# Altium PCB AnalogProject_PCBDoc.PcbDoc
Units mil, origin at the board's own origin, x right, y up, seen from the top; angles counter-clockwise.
Board outline 2357.65 x 1577.53 mil, 2 copper layers (Top Layer, Bottom Layer); 20 components, 11 nets, 48 pads, 3 vias.
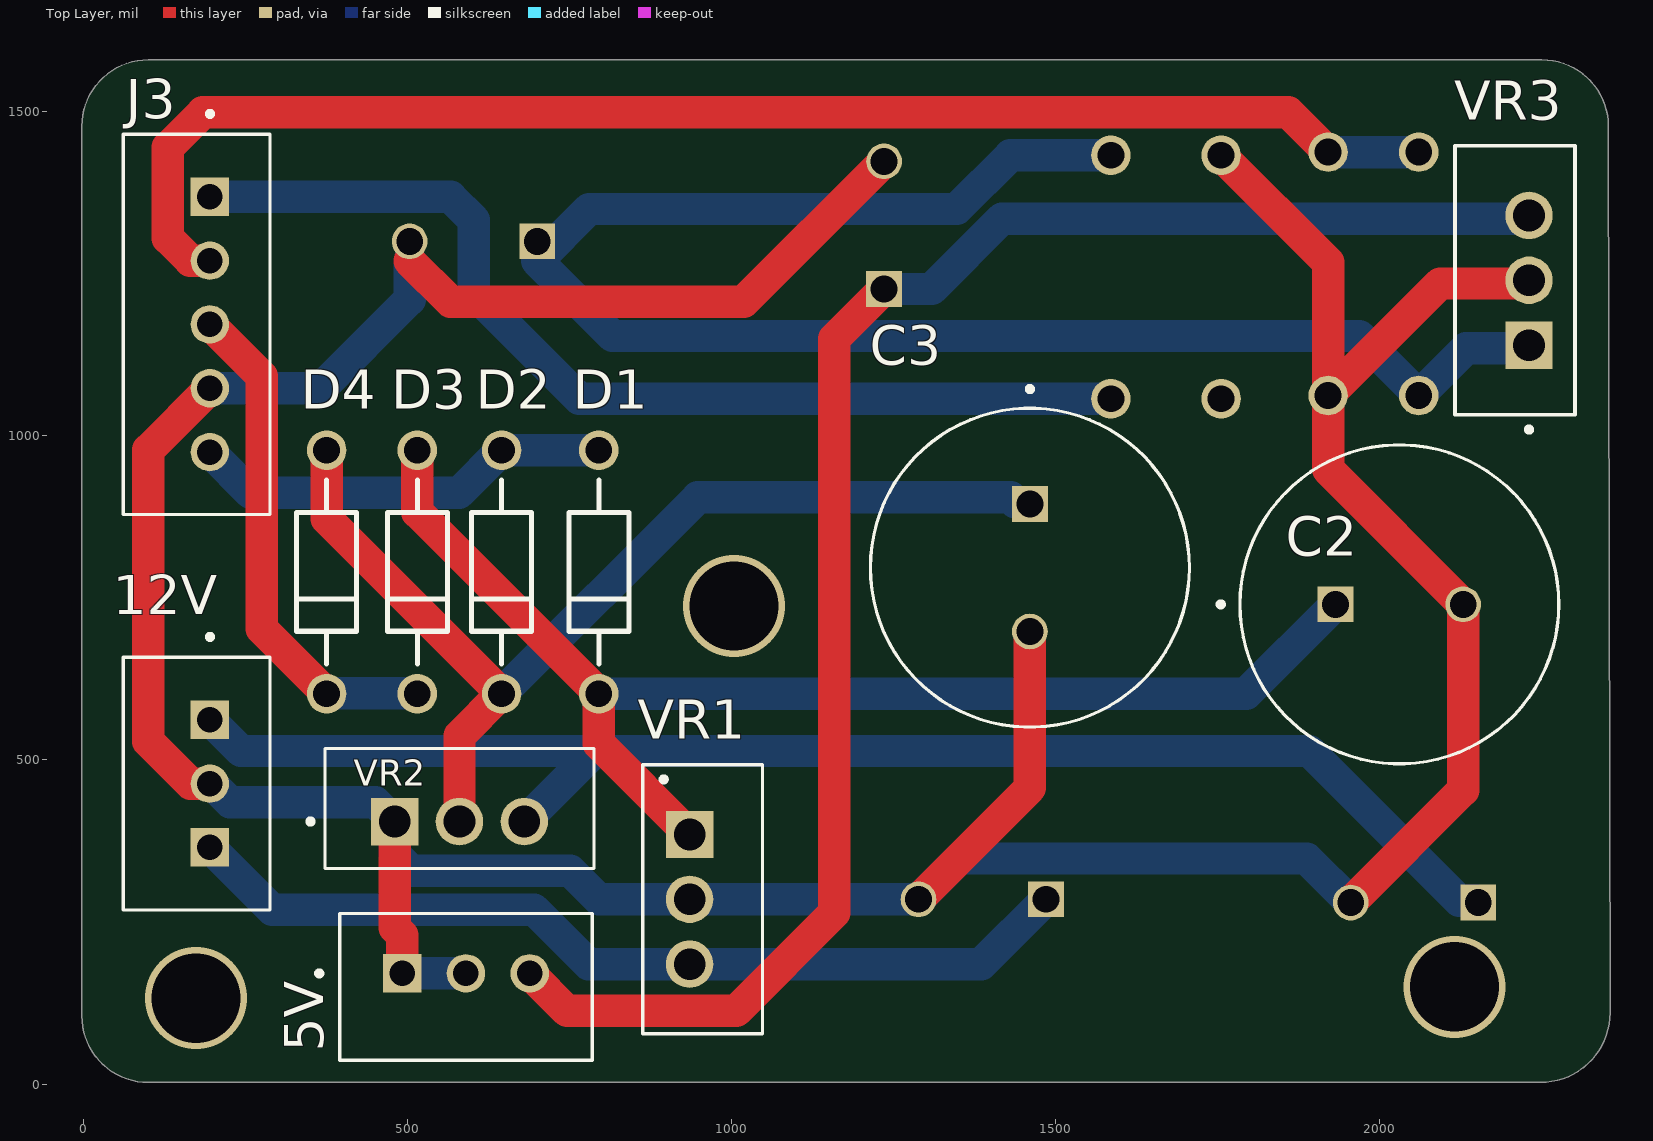
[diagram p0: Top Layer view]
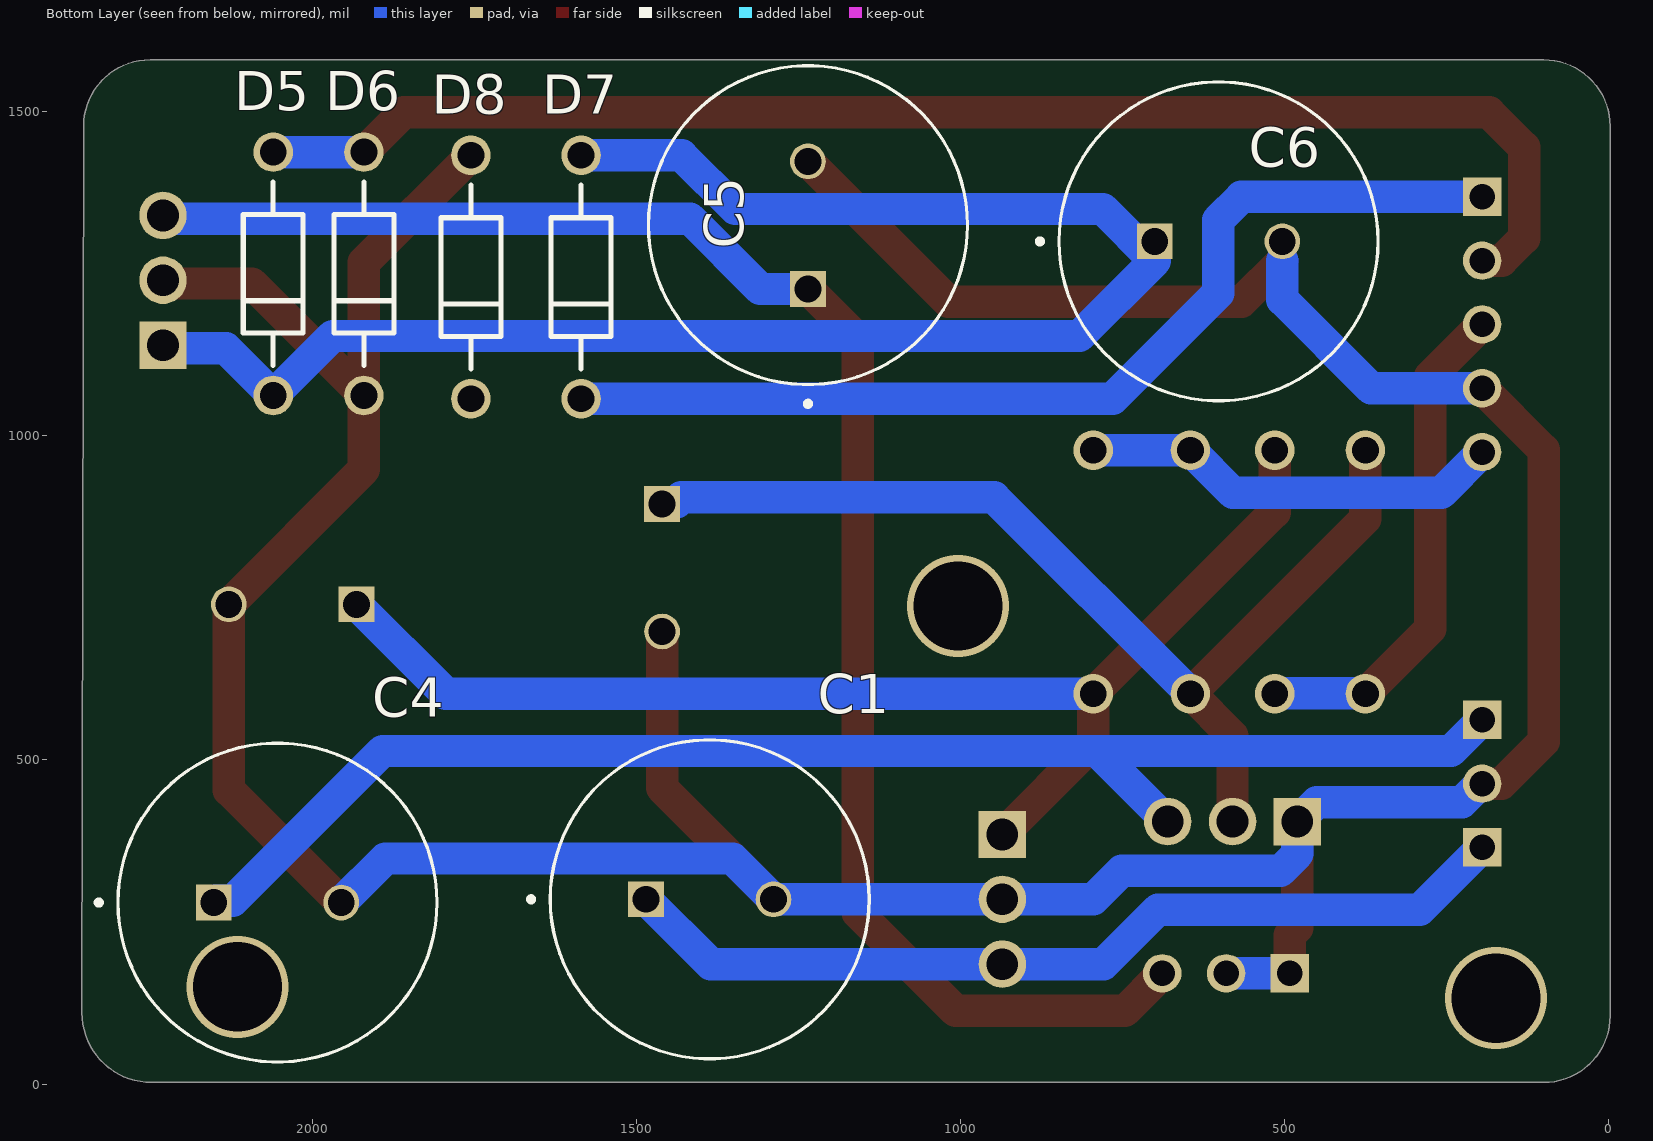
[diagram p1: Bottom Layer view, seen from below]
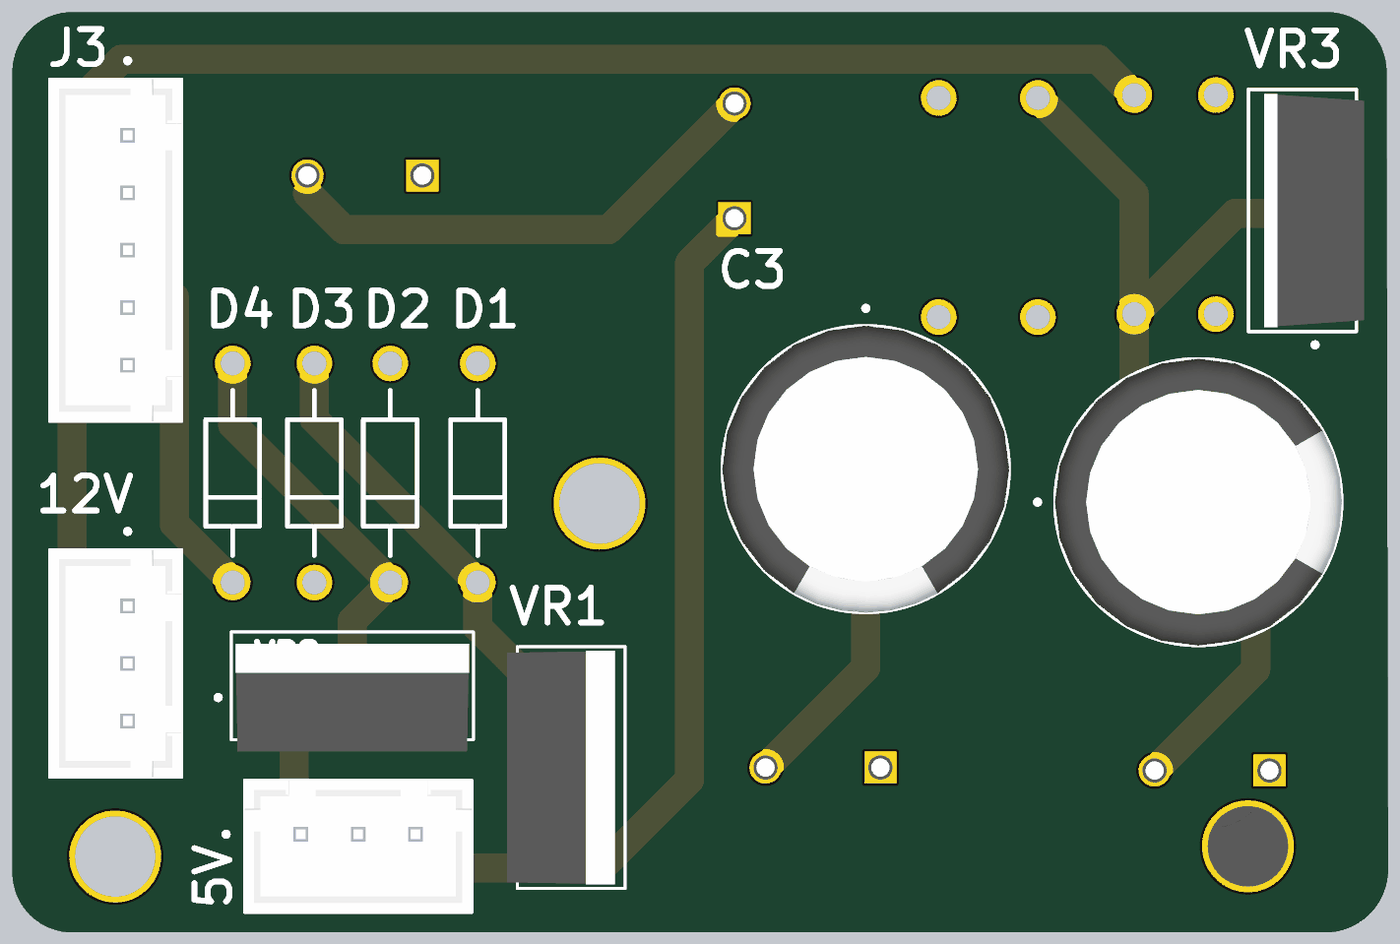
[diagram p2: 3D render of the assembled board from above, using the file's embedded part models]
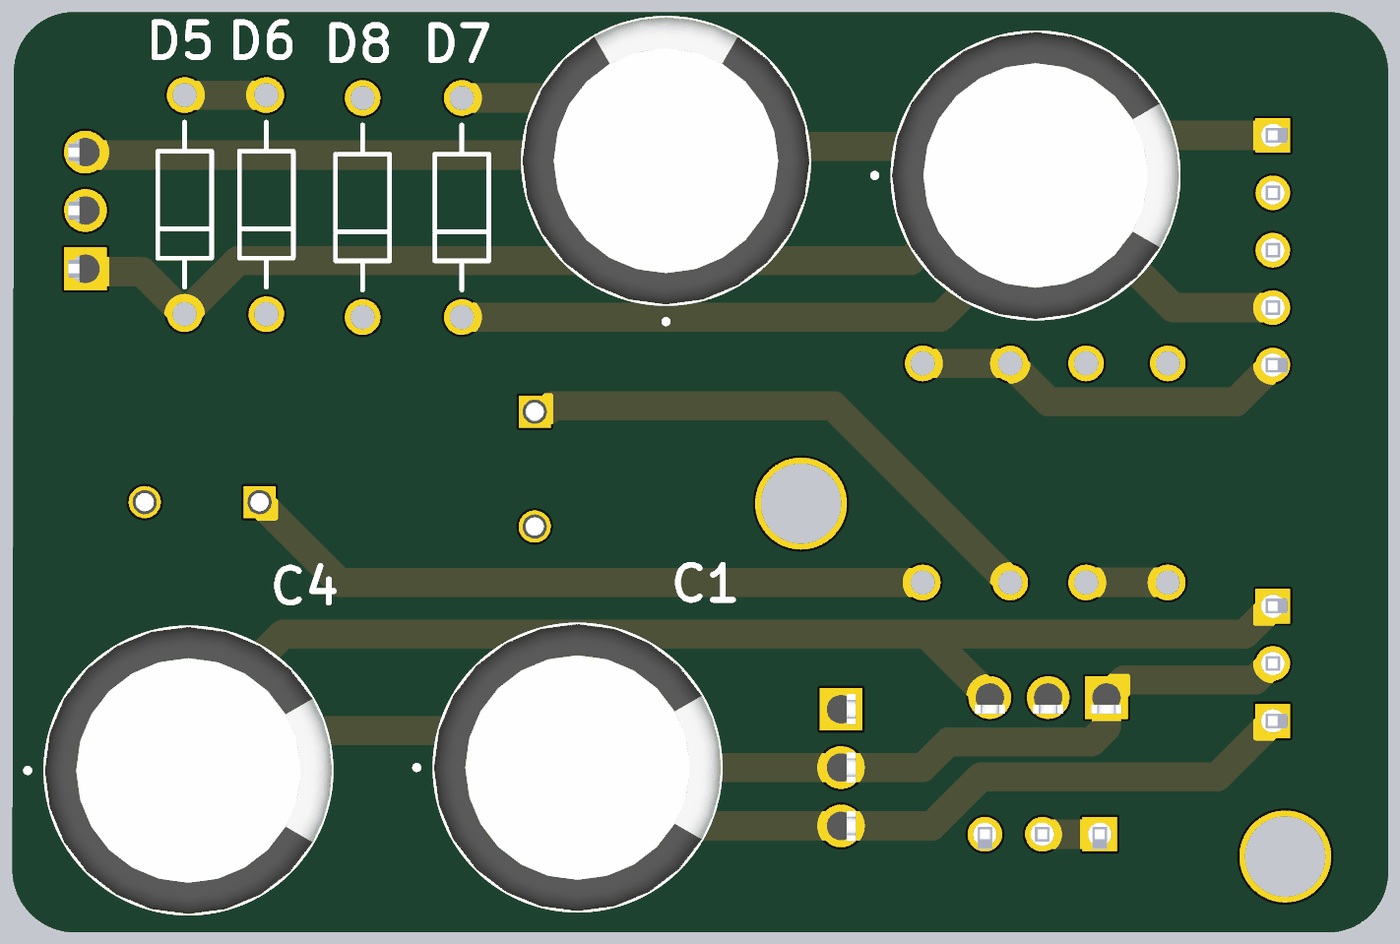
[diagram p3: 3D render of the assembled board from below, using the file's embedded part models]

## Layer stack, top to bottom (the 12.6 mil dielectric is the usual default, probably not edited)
Top Solder: solder mask 0.4, Solder Resist, Dk 3.5
Top Layer: signal copper 1.4
Dielectric 1: dielectric 12.6, FR-4, Dk 4.8
Bottom Layer: signal copper 1.4
Bottom Solder: solder mask 0.4, Solder Resist, Dk 3.5

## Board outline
-2.53,105 ccw(c100,105) 100,2.47 2247.47,2.47 ccw(c2247.47,110.12) 2355.12,110.12 2352.53,1477.47 ccw(c2250,1477.47) 2250,1580 100,1580 ccw(c100,1477.47) -2.53,1477.47

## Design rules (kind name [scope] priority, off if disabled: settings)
Clearance [All] p1: gap=10 ignorepadtopadclearanceinfootprint=FALSE
Height [All] p1: minheight=0 maxheight=2362.2 prefheight=500
PolygonConnect [All] p1: connectstyle=Relief reliefconductorwidth=10 reliefentries=4 polygonreliefangle="90 Angle" airgapwidth=10
RoutingVias [All] p1: holewidth=28 width=50 viastyle="Through Hole" minholewidth=28 minwidth=50 maxholewidth=28 maxwidth=50
SolderMaskExpansion [All] p1: expansion=4 istentingtop=FALSE
SupplyNets "Schematic Supply Nets" [InNet('GND')] p1: voltage=0.000
Width [All] p1: maxlimit=60 minlimit=30 preferedwidth=50
29 further rules are at their usual default settings.

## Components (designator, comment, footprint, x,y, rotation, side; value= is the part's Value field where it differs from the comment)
5V "+" JST_B3B-XH-A#1 590,150 r180 top (schematic designator J1)
12V "+" JST_B3B-XH-A#2 174.33,463.43 r90 top (schematic designator J2)
C1 "2200uF Cap" "2200uF Cap" 1386.57,285 r180 bottom
C2 "2200uF Cap" "2200uF Cap" 2030,740 r0 top
C3 "2200uF Cap" "2200uF Cap" 1460,796.57 r270 top
C4 "2200uF Cap" "2200uF Cap" 2053.43,280 r180 bottom
C5 "2200uF Cap" "2200uF Cap" 1235,1325 r90 bottom
C6 "2200uF Cap" "2200uF Cap" 601.57,1300 r180 bottom
D1 "1N4001G" 1N4001_diode 795,790 r90 top
D2 "1N4001G" 1N4001_diode 645,790 r90 top
D3 "1N4001G" 1N4001_diode 515,790 r90 top
D4 "1N4001G" 1N4001_diode 375,790 r90 top
D5 "1N4001G" 1N4001_diode 2060,1250 r90 bottom
D6 "1N4001G" 1N4001_diode 1920,1250 r90 bottom
D7 "1N4001G" 1N4001_diode 1585,1245 r90 bottom
D8 "1N4001G" 1N4001_diode 1755,1245 r90 bottom
J3 "B5B-XH-A" JST_B5B-XH-A 174.33,1171.85 r90 top
VR1 "LM7812CT/NOPB" LM7812 935,285 r270 top
VR2 "LM7912CT/NOPB" LM7912 580,405 r0 top
VR3 "LM7805CT/NOPB" LM7805 2230,1140 r90 top

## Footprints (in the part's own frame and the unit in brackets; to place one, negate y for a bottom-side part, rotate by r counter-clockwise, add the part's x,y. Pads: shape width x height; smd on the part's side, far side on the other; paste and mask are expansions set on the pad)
1N4001_diode [mm] "AXIAL, 2-Leads, Diameter 2.35mm"
  round 1.55 hole 1.05: 1(-4.77,0) 2(4.77,0)
  silkscreen extent -3.6,-1.18 3.6,1.18
"2200uF Cap" [mm]
  rect 1.4x1.4 hole 1.05: 1(-2.5,0)
  round 1.4 hole 1.05: 2(2.5,0)
  silkscreen extent -7.1,-6.25 6.25,6.25, body extent -6.22,-6.25 6.25,6.25, height 35
JST_B3B-XH-A#1 [mm]
  rect 1.508x1.508 / inner round 1.508 / far side rect 1.508x1.508 hole 1: 1(2.5,-0.525)
  round 1.508 hole 1: 2(0,-0.525) 3(-2.5,-0.525)
  silkscreen extent -4.95,-2.88 5.85,2.87, body extent -4.95,-2.88 4.95,2.88, height 7
JST_B3B-XH-A#2 [mm]
  rect 1.508x1.508 / inner round 1.508 / far side rect 1.508x1.508 hole 1: 1(2.5,-0.525)
  round 1.508 hole 1: 2(0,-0.525)
  rect 1.508x1.508 hole 1: 3(-2.5,-0.525)
  silkscreen extent -4.95,-2.88 5.85,2.87, body extent -4.95,-2.88 4.95,2.88, height 7
JST_B5B-XH-A [mm]
  rect 1.508x1.508 / inner round 1.508 / far side rect 1.508x1.508 hole 1: 1(5,-0.525)
  round 1.508 hole 1: 2(2.5,-0.525) 3(0,-0.525) 4(-2.5,-0.525) 5(-5,-0.525)
  silkscreen extent -7.45,-2.88 8.35,2.87, body extent -7.45,-2.88 7.45,2.88, height 7
LM7805 [mm]
  rect 1.86x1.86 / inner round 1.86 / far side rect 1.86x1.86 hole 1.24: 1(0,0)
  round 1.86 hole 1.24: 2(2.54,0) 3(5.08,0)
  silkscreen extent -3.41,-1.8 7.81,2.9, body extent -2.54,-2.14 7.62,2.21, height 20.4
LM7812 [mm]
  rect 1.86x1.86 / inner round 1.86 / far side rect 1.86x1.86 hole 1.24: 1(-2.54,0)
  round 1.86 hole 1.24: 2(0,0) 3(2.54,0)
  silkscreen extent -5.27,-1.84 5.27,2.86, body extent -5.08,-2.29 5.08,2.41, height 15.49
LM7912 [mm]
  rect 1.86x1.86 / inner round 1.86 / far side rect 1.86x1.86 hole 1.24: 1(-2.54,0)
  round 1.86 hole 1.24: 2(0,0) 3(2.54,0)
  silkscreen extent -5.94,-1.84 5.27,2.86, body extent -5.08,-2.35 5.08,2.35, height 15.49

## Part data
5V 12V: library part B3B-XH-A, "Connector Header Through Hole 3 position 0.098 (2.50mm)", Package=None
C1 C2 C3 C4 C5 C6: "2200 ÂµF 25 V Aluminum Electrolytic Capacitors Radial, Can - 5000 Hrs @ 105Â°C", Package="RADIAL-2 Panasonic"
D1 D2 D3 D4 D5 D6 D7 D8: library part CMP-0902-00120-1, "Diode, Rectifier, Standard, Vr 50V, If 1A, Pkg SOD57, Vf 0.93V, Tj +175C, Cs 30A, Ir 1UA", Average Rectified Current=1A, Breakdown Voltage=50V, Forward Voltage=1.1V, Manufacturer="On Semiconductor", Manufacturer Lifecycle Status=ACTIVE, Max Forward Surge Current (Ifsm)=30A, Max Operating Temperature=150°C, Min Operating Temperature=-65°C, Peak Reverse Current=10µA, Supplier Part Number=1N4001GOS-ND
J3: "Connector Header Through Hole 5 position 0.098 (2.50mm)", Package=None
VR1: "1.5-A, 30-V, linear voltage regulator", Package="TO-220-3 Texas Instruments"
VR2: "1.5-A, negative linear voltage regulator", Package="TO-220-3 Texas Instruments"
VR3: "Linear Voltage Regulator IC Positive Fixed 1 Output 1.5A TO-220-3", Package="TO-220-3 ON Semiconductor"

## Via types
v1: diameter 157.48, hole 137.8, Top Layer to Bottom Layer, 3 vias

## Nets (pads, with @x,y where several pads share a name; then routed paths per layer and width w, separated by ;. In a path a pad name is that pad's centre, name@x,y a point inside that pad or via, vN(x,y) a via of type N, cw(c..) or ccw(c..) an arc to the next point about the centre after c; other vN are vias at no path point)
5V: 5V.3 C5.1 VR3.3 | length 2592.5
  Top Layer w50: 5V.3 746.1,113 1007,113 1158,264 1158,1149.57 C5.1
  Bottom Layer w50: C5.1 1308.57,1226.57 1417,1335 2208.58,1335 2209.13,1335.56 2225.56,1335.56 VR3.3
+Vs: 12V.3 C1.1 VR1.3 | length 1406
  Bottom Layer w50: 12V.3 291,269 695,269 779,185 VR1.3 1385,185 C1.1
-Vs: 12V.1 C4.1 VR2.3 | length 2227.5
  Bottom Layer w50: 12V.1 243,513.85 788.85,513.85 ; VR2.3 788.85,513.85 ; C4.1 2149.29,282.56 2122.44,282.56 1891.15,513.85 788.85,513.85
GND: 5V.1 5V.2 12V.2 C1.2 C2.2 C3.2 C4.2 C5.2 C6.2 D6.1 D8.2 J3.4 VR1.2 VR2.1 VR3.2 | length 6480.8
  Top Layer w50: 12V.2 165,463.43 100,528.43 100,978.43 J3.4 ; VR2.1 480,241.39 491.57,229.82 5V.1 ; 503.15,1270 566.15,1207 1018.57,1207 C5.2 ; C1.2 1460,456.85 C3.2 ; D8.2 1920,1267.8 D6.1 ; C4.2 2128.43,453.43 C2.2 1920,948.43 D6.1 ; VR3.2 2225.56,1235.56 2209.13,1235.56 2208.58,1235 2092.8,1235 D6.1
  Bottom Layer w50: 12V.2 197.54,463.43 225.96,435 450,435 VR2.1 480,355 506,329 751,329 795,285 VR1.2 C1.2 1351.15,348 1887,348 C4.2 ; J3.4 366.43,1073.43 503.15,1210.15 503.15,1270 ; 5V.1 5V.2
NetC2_1: C2.1 D1.1 D3.2 VR1.1 | length 1960.4
  Top Layer w50: D3.2 515,882.2 D1.1 795,525 VR1.1
  Bottom Layer w50: D1.1 1793.78,602.2 C2.1
NetC3_1: C3.1 D2.1 D4.2 VR2.2 | length 1656.1
  Top Layer w50: D4.2 375,872.2 D2.1 580,537.2 VR2.2
  Bottom Layer w50: D2.1 947.8,905 1430.24,905 1437.68,897.56 1457.44,897.56 C3.1
NetC6_1: C6.1 D5.1 D7.2 VR3.1 | length 2600.7
  Bottom Layer w50: D7.2 1429.8,1432.8 1347.01,1350 780,1350 700,1270 816,1154 1968.2,1154 D5.1 2132.8,1135 2225,1135 VR3.1
NetD1_2: D1.2 D2.2 J3.5 | length 653.3
  Bottom Layer w50: J3.5 258,912 579.2,912 D2.2 D1.2
NetD3_1: D3.1 D4.1 J3.3 | length 784.5
  Top Layer w50: J3.3 275,1091.85 275,702.2 D4.1
  Bottom Layer w50: D4.1 375.38,602.59 514.62,602.59 D3.1
NetD5_2: D5.2 D6.2 J3.2 | length 2197.1
  Top Layer w50: J3.2 164.72,1270.28 130,1305 130,1445 184,1499 1858.8,1499 D6.2
  Bottom Layer w50: D6.2 D5.2
NetD7_1: D7.1 J3.1 | length 1585.1
  Bottom Layer w50: J3.1 566.3,1368.7 602,1333 602,1220.2 765,1057.2 D7.1
pads on no net: D8.1
copper on no net:
  other v1: 173.63,132.51 2115,150 1003.63,737.51

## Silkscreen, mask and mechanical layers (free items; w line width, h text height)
Mechanical 1:
  lines w10: -2.53,105 ccw(c100,105) 100,2.47 2247.47,2.47 ccw(c2247.47,110.12) 2355.12,110.12 2352.53,1477.47 ccw(c2250,1477.47) 2250,1580 2200,1580 100,1580 ccw(c100,1477.47) -2.53,1477.47 -2.53,105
